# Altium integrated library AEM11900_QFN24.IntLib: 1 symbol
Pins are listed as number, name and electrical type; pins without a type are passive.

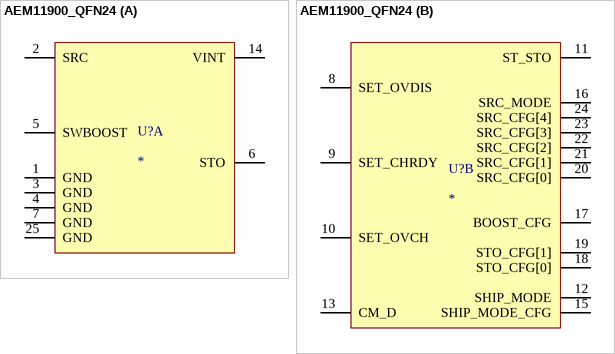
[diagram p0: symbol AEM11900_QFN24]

## AEM11900_QFN24
designator U?
part A pins: 1 GND, 2 SRC, 3 GND, 4 GND, 5 SWBOOST, 6 STO, 7 GND, 14 VINT, 25 GND
part B pins: 8 SET_OVDIS, 9 SET_CHRDY, 10 SET_OVCH, 11 ST_STO, 12 SHIP_MODE, 13 CM_D, 15 SHIP_MODE_CFG, 16 SRC_MODE, 17 BOOST_CFG, 18 STO_CFG[0], 19 STO_CFG[1], 20 SRC_CFG[0], 21 SRC_CFG[1], 22 SRC_CFG[2], 23 SRC_CFG[3], 24 SRC_CFG[4]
